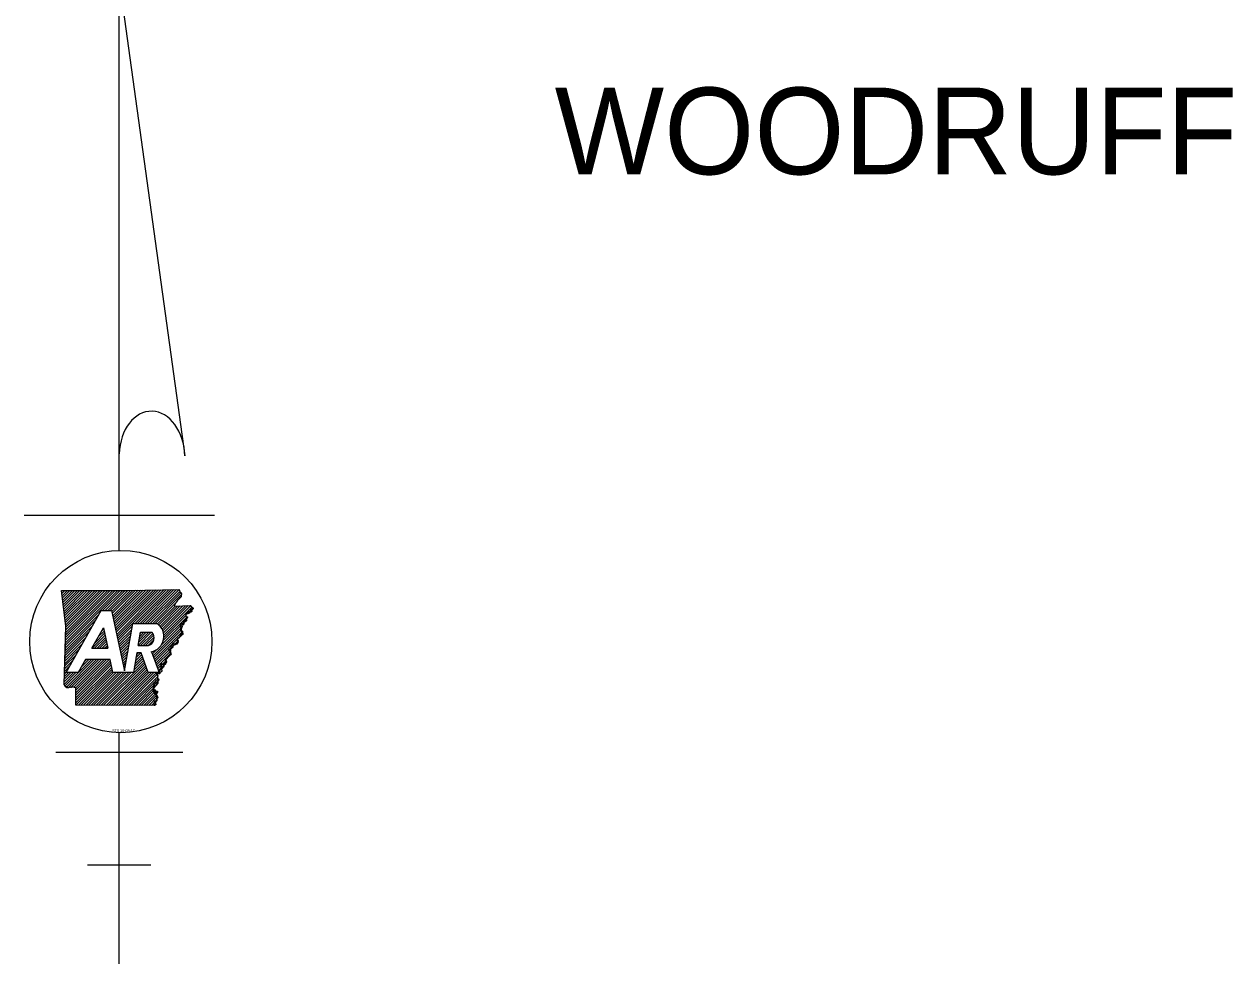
# Model space of a CAD drawing. Extents: x -24122 to 24238, y -8840 to 11381.
# Drawn here: x -13734 to -10389, y 3625 to 6225 of the extents above; entities that cross this region are included whole.
import ezdxf

# ---------------------------------------------------------------- set-up
doc = ezdxf.new("R2010")
doc.units = 0
doc.layers.add('R_Annotation', color=7, linetype='Continuous')
doc.layers.add('R_Border', color=7, linetype='Continuous')

msp = doc.modelspace()

# ---------------------------------------------------------------- linework, layer by layer
at = {"layer": 'R_Annotation'}
for p, q in [((-13470.5, 6345), (-13288.7, 5030.9)), ((-13470.5, 4769.2), (-13470.5, 6345)), ((-13733.7, 4866.6), (-13207.4, 4866.6)), ((-13630.2, 4656.3), (-13628, 4658.4)), ((-13629.4, 4650.1), (-13621, 4658.4)), ((-13628.6, 4643.9), (-13614.1, 4658.4)), ((-13627.9, 4637.7), (-13607.1, 4658.4)), ((-13627.1, 4631.5), (-13600.2, 4658.4)), ((-13626.3, 4625.3), (-13593.2, 4658.4)), ((-13625.6, 4619.1), (-13586.2, 4658.4)), ((-13624.8, 4612.9), (-13579.3, 4658.4)), ((-13624, 4606.7), (-13572.3, 4658.4)), ((-13623.2, 4600.5), (-13565.4, 4658.4)), ((-13622.5, 4594.3), (-13558.4, 4658.4)), ((-13621.7, 4588.1), (-13551.4, 4658.4)), ((-13620.9, 4581.9), (-13544.5, 4658.4)), ((-13620.2, 4575.7), (-13537.5, 4658.4)), ((-13619.9, 4506.3), (-13467.7, 4658.5)), ((-13619.7, 4513.5), (-13474.7, 4658.5)), ((-13619.4, 4520.7), (-13481.7, 4658.5)), ((-13619.4, 4569.5), (-13530.5, 4658.4)), ((-13619.2, 4527.9), (-13488.7, 4658.5)), ((-13619, 4535.1), (-13495.6, 4658.5)), ((-13618.7, 4542.3), (-13502.6, 4658.4)), ((-13618.6, 4563.4), (-13523.6, 4658.4)), ((-13618.5, 4549.5), (-13509.6, 4658.4)), ((-13618.2, 4556.8), (-13516.6, 4658.4)), ((-13516.5, 4602.8), (-13460.7, 4658.5)), ((-13509.5, 4602.8), (-13453.8, 4658.6)), ((-13502.5, 4602.8), (-13446.7, 4658.6)), ((-13495.6, 4602.8), (-13439.7, 4658.7)), ((-13491.2, 4600.2), (-13432.6, 4658.8)), ((-13490, 4594.4), (-13425.5, 4658.9)), ((-13488.8, 4588.7), (-13418.4, 4659)), ((-13487.6, 4583), (-13411.3, 4659.2)), ((-13486.3, 4577.2), (-13404.3, 4659.3)), ((-13485.1, 4571.5), (-13397.2, 4659.4)), ((-13483.9, 4565.7), (-13390.1, 4659.5)), ((-13482.6, 4560), (-13383, 4659.6)), ((-13481.4, 4554.3), (-13376, 4659.7)), ((-13480.2, 4548.5), (-13368.9, 4659.8)), ((-13479, 4542.8), (-13361.8, 4659.9)), ((-13477.7, 4537), (-13354.7, 4660)), ((-13476.5, 4531.3), (-13347.6, 4660.2)), ((-13475.3, 4525.6), (-13340.5, 4660.3)), ((-13426.9, 4567), (-13333.4, 4660.5)), ((-13419.9, 4567), (-13326.3, 4660.7)), ((-13413, 4567), (-13319.1, 4660.8)), ((-13406, 4567), (-13312, 4661)), ((-13399, 4567), (-13304.9, 4661.2)), ((-13392.1, 4567), (-13303.3, 4655.8)), ((-13385.1, 4567), (-13299.9, 4652.2)), ((-13378.1, 4567), (-13299, 4646.1)), ((-13371.2, 4567), (-13314.9, 4623.2)), ((-13354.6, 4555.7), (-13294.3, 4616)), ((-13352, 4551.3), (-13286.9, 4616.4)), ((-13349.9, 4546.5), (-13279.6, 4616.8)), ((-13348.3, 4541.1), (-13273, 4616.4)), ((-13620.2, 4499.1), (-13526.2, 4593.1)), ((-13617.8, 4431.2), (-13520.7, 4602.8)), ((-13520.7, 4602.8), (-13491.8, 4602.8)), ((-13364.8, 4566.4), (-13316.3, 4614.9)), ((-13361, 4563.2), (-13309, 4615.3)), ((-13357.6, 4559.6), (-13301.6, 4615.6)), ((-13348.8, 4519.7), (-13285.6, 4582.9)), ((-13347.4, 4535.1), (-13269.7, 4612.7)), ((-13347.3, 4528.1), (-13286.4, 4589.1)), ((-13272.8, 4602.6), (-13266.5, 4609)), ((-13620.6, 4484.7), (-13544.4, 4561)), ((-13620.4, 4491.9), (-13535.3, 4577)), ((-13546.4, 4498.5), (-13514.6, 4554.7)), ((-13519.5, 4545.9), (-13513.9, 4551.6)), ((-13474.1, 4519.8), (-13434.5, 4559.4)), ((-13472.8, 4514.1), (-13436, 4550.9)), ((-13433.2, 4567), (-13365.7, 4567)), ((-13377.5, 4477), (-13300.3, 4554.3)), ((-13354.8, 4506.7), (-13301.6, 4559.9)), ((-13293.4, 4568.2), (-13284.8, 4576.8)), ((-13621.1, 4470.3), (-13562.5, 4528.9)), ((-13620.9, 4477.5), (-13553.4, 4544.9)), ((-13546, 4498.5), (-13510.2, 4534.3)), ((-13539.1, 4498.5), (-13509, 4528.6)), ((-13537.7, 4513.8), (-13511.5, 4540.1)), ((-13532.1, 4498.5), (-13507.8, 4522.9)), ((-13528.6, 4529.9), (-13512.7, 4545.8)), ((-13525.1, 4498.5), (-13506.6, 4517.1)), ((-13471.6, 4508.4), (-13437.5, 4542.5)), ((-13470.4, 4502.6), (-13438.9, 4534.1)), ((-13469.1, 4496.9), (-13440.4, 4525.6)), ((-13467.9, 4491.1), (-13441.9, 4517.2)), ((-13418.5, 4506.1), (-13381.9, 4542.8)), ((-13417.1, 4514.5), (-13388.8, 4542.8)), ((-13415.6, 4523), (-13395.8, 4542.8)), ((-13414.1, 4531.4), (-13402.8, 4542.8)), ((-13412.7, 4539.8), (-13409.7, 4542.8)), ((-13412.2, 4542.8), (-13380.5, 4542.8)), ((-13411.5, 4506.1), (-13378, 4539.7)), ((-13404.6, 4506.1), (-13375.6, 4535.1)), ((-13397.6, 4506.1), (-13374.3, 4529.4)), ((-13390.6, 4506.1), (-13374.9, 4521.8)), ((-13375.7, 4471.9), (-13299, 4548.6)), ((-13373.8, 4466.9), (-13297.7, 4542.9)), ((-13371.9, 4461.8), (-13296.4, 4537.3)), ((-13320.2, 4506.5), (-13310.4, 4516.3)), ((-13621.6, 4455.9), (-13580.7, 4496.8)), ((-13621.4, 4463.1), (-13571.6, 4512.8)), ((-13546.4, 4498.5), (-13502.6, 4498.5)), ((-13518.2, 4498.5), (-13505.3, 4511.4)), ((-13511.2, 4498.5), (-13504.1, 4505.7)), ((-13504.2, 4498.5), (-13502.9, 4499.9)), ((-13466.7, 4485.4), (-13443.3, 4508.7)), ((-13465.5, 4479.7), (-13444.8, 4500.3)), ((-13464.2, 4473.9), (-13446.3, 4491.9)), ((-13463, 4468.2), (-13447.8, 4483.4)), ((-13424.5, 4471.8), (-13410.6, 4485.8)), ((-13423.1, 4480.3), (-13417.6, 4485.8)), ((-13410.4, 4485.8), (-13422.1, 4485.8)), ((-13418.5, 4506.1), (-13389.6, 4506.1)), ((-13390.2, 4431.2), (-13410.4, 4485.8)), ((-13381.8, 4488.7), (-13360.6, 4431.2)), ((-13381.3, 4487.2), (-13379.2, 4489.3)), ((-13379.4, 4482.1), (-13366.2, 4495.4)), ((-13370, 4456.7), (-13328.2, 4498.5)), ((-13368.1, 4451.6), (-13329, 4490.7)), ((-13366.3, 4446.5), (-13329.8, 4483)), ((-13622.3, 4434.3), (-13608, 4448.6)), ((-13622.1, 4441.5), (-13598.9, 4464.6)), ((-13621.8, 4448.7), (-13589.8, 4480.7)), ((-13620.8, 4394), (-13547.6, 4467.2)), ((-13616.7, 4391.2), (-13540.6, 4467.2)), ((-13611.7, 4389.2), (-13533.7, 4467.2)), ((-13603.4, 4390.5), (-13526.7, 4467.2)), ((-13596.3, 4390.6), (-13519.7, 4467.2)), ((-13590.9, 4389.1), (-13512.8, 4467.2)), ((-13590.6, 4375.4), (-13498.8, 4467.2)), ((-13590.6, 4382.4), (-13505.8, 4467.2)), ((-13590.6, 4368.5), (-13495.2, 4463.9)), ((-13590.6, 4361.5), (-13493.9, 4458.2)), ((-13590.5, 4354.6), (-13492.7, 4452.4)), ((-13564.1, 4467.2), (-13584.5, 4431.2)), ((-13576.6, 4445.1), (-13554.6, 4467.2)), ((-13567.5, 4461.2), (-13561.5, 4467.2)), ((-13495.9, 4467.2), (-13564.1, 4467.2)), ((-13520.9, 4340.7), (-13401.1, 4460.5)), ((-13513.9, 4340.7), (-13399.2, 4455.4)), ((-13507, 4340.6), (-13397.3, 4450.3)), ((-13461.8, 4462.5), (-13449.2, 4475)), ((-13460.5, 4456.7), (-13450.7, 4466.6)), ((-13459.3, 4451), (-13452.2, 4458.1)), ((-13458.1, 4445.2), (-13453.6, 4449.7)), ((-13430.4, 4438.1), (-13402.9, 4465.6)), ((-13428.9, 4446.5), (-13404.8, 4470.7)), ((-13427.5, 4455), (-13406.7, 4475.7)), ((-13426, 4463.4), (-13408.6, 4480.8)), ((-13364.4, 4441.4), (-13343, 4462.8)), ((-13362.5, 4436.3), (-13346, 4452.8)), ((-13623.4, 4398.4), (-13590.6, 4431.2)), ((-13623.3, 4405.5), (-13597.5, 4431.2)), ((-13623, 4412.7), (-13604.5, 4431.2)), ((-13622.8, 4419.9), (-13611.5, 4431.2)), ((-13622.5, 4427.1), (-13617.1, 4432.5)), ((-13584.5, 4431.2), (-13617.8, 4431.2)), ((-13590.5, 4347.6), (-13491.5, 4446.7)), ((-13590.4, 4340.8), (-13490.2, 4440.9)), ((-13583.5, 4340.8), (-13489, 4435.2)), ((-13576.5, 4340.8), (-13486.1, 4431.2)), ((-13569.5, 4340.8), (-13479.1, 4431.2)), ((-13562.6, 4340.7), (-13472.1, 4431.2)), ((-13555.6, 4340.7), (-13465.2, 4431.2)), ((-13548.7, 4340.7), (-13458.2, 4431.2)), ((-13541.7, 4340.7), (-13451.2, 4431.2)), ((-13534.8, 4340.7), (-13444.3, 4431.2)), ((-13527.8, 4340.7), (-13437.3, 4431.2)), ((-13500, 4340.6), (-13395.4, 4445.2)), ((-13493.1, 4340.6), (-13393.5, 4440.1)), ((-13431.6, 4431.2), (-13488.2, 4431.2)), ((-13486.1, 4340.6), (-13391.7, 4435)), ((-13479.1, 4340.6), (-13388.6, 4431.2)), ((-13472.2, 4340.6), (-13381.6, 4431.2)), ((-13465.2, 4340.6), (-13374.6, 4431.2)), ((-13458.3, 4340.6), (-13367.7, 4431.2)), ((-13456.9, 4439.5), (-13455.1, 4441.3)), ((-13451.3, 4340.6), (-13365.3, 4426.6)), ((-13444.4, 4340.5), (-13365, 4419.9)), ((-13360.6, 4431.2), (-13390.2, 4431.2)), ((-13437.4, 4340.5), (-13364.7, 4413.2)), ((-13430.5, 4340.5), (-13364.4, 4406.6)), ((-13423.5, 4340.5), (-13375.8, 4388.2)), ((-13416.6, 4340.5), (-13373.7, 4383.4)), ((-13409.6, 4340.5), (-13371.5, 4378.6)), ((-13402.6, 4340.5), (-13369.4, 4373.7)), ((-13395.7, 4340.5), (-13367.2, 4368.9)), ((-13388.7, 4340.5), (-13365.4, 4363.8)), ((-13381.8, 4340.4), (-13368.6, 4353.6)), ((-13374.8, 4340.4), (-13371.7, 4343.5)), ((-13470.5, 3625.5), (-13470.5, 4265.1)), ((-13646, 4210.7), (-13295.1, 4210.7)), ((-13558.3, 3899.1), (-13382.8, 3899.1))]:
    msp.add_line(p, q, dxfattribs=at)
for points in [[(-13630.5, 4658.4), (-13534.4, 4658.4), (-13450, 4658.6), (-13350.5, 4660.1), (-13304.4, 4661.2)], [(-13630.5, 4658.4), (-13534.4, 4658.4), (-13450, 4658.6), (-13350.5, 4660.1), (-13304.4, 4661.2)], [(-13619.8, 4509), (-13618.2, 4559.7), (-13630.5, 4658.4)], [(-13623.5, 4398.4), (-13618.1, 4559.7), (-13630.5, 4658.4)], [(-13274.2, 4617), (-13265.9, 4608.3), (-13286.6, 4591.3), (-13284.4, 4574.1), (-13302.2, 4562.4), (-13296.1, 4535.9), (-13309.8, 4523.4), (-13311, 4509.8), (-13327.7, 4503.8), (-13330.3, 4478.2), (-13342.3, 4465.3), (-13348.1, 4446), (-13365.5, 4430.1), (-13364.2, 4401.9), (-13376, 4388.6), (-13365.2, 4364.4), (-13372.7, 4340.4)], [(-13318.7, 4614.8), (-13273.6, 4617.1)], [(-13318.7, 4614.8), (-13273.6, 4617.1)], [(-13491.8, 4602.8), (-13456.1, 4435.8), (-13433.2, 4567)], [(-13514.6, 4554.7), (-13502.6, 4498.5)], [(-13418.5, 4506.1), (-13412.2, 4542.8)], [(-13623.5, 4398.4), (-13619.8, 4509)], [(-13422.1, 4485.8), (-13431.6, 4431.2)], [(-13488.2, 4431.2), (-13495.9, 4467.2)], [(-13372.7, 4340.4), (-13590.5, 4340.8), (-13590.6, 4388.9)], [(-13372.7, 4340.4), (-13590.5, 4340.8), (-13590.6, 4388.9)]]:
    msp.add_lwpolyline(points, dxfattribs=at)
for centre, major_axis, ratio, start_param, end_param in [((-13379.7, 5028.1), (-3.9, 126.3), 0.719778, 4.712385, 7.768526), ((-13390.8, 4531.3), (-43.6, 0), 0.999987, 1.777838, 4.099264), ((-13396.5, 4527.3), (-22.3, 0), 0.999987, 1.887169, 3.90762)]:
    msp.add_ellipse(centre, major_axis=major_axis, ratio=ratio, start_param=start_param, end_param=end_param, dxfattribs=at)
msp.add_ellipse((-13466.4, 4517.1), major_axis=(252.1, 0), ratio=0.999976, dxfattribs=at)
for points in [[(-13304.4, 4661.2), (-13304.1, 4658.6), (-13303.3, 4657.2), (-13303.2, 4654.7), (-13302.2, 4653.6), (-13300.4, 4652.5), (-13298.9, 4650.8), (-13298.5, 4648.8), (-13299, 4646.8), (-13299.1, 4644.4), (-13299.4, 4642.4), (-13299.8, 4640.6), (-13301.1, 4639.1), (-13302.5, 4638), (-13303.7, 4636.8), (-13304.6, 4635.4), (-13306.2, 4634), (-13307.7, 4632.5), (-13309, 4631.2), (-13310.3, 4629.6), (-13310.9, 4627.7), (-13312.2, 4626.4), (-13313.3, 4625.2), (-13314.7, 4623.6), (-13315.4, 4622), (-13316.7, 4620.2), (-13317.1, 4618.4), (-13317.9, 4617), (-13318, 4616.7)], [(-13304.4, 4661.2), (-13304.1, 4658.6), (-13303.3, 4657.2), (-13303.2, 4654.7), (-13302.2, 4653.6), (-13300.4, 4652.6), (-13298.9, 4650.8), (-13298.5, 4648.8), (-13299, 4646.7), (-13299.1, 4644.4), (-13299.4, 4642.4), (-13299.7, 4640.6), (-13301.1, 4639.1), (-13302.5, 4638), (-13303.8, 4636.7), (-13304.7, 4635.4), (-13306.2, 4634), (-13307.7, 4632.5), (-13309, 4631.2), (-13310.2, 4629.6), (-13310.8, 4627.7), (-13312.2, 4626.4), (-13313.3, 4625.2), (-13314.7, 4623.6), (-13315.4, 4622), (-13316.8, 4620.2), (-13317.1, 4618.4), (-13318, 4617), (-13318, 4616.7)], [(-13274.2, 4617), (-13273.6, 4617.1), (-13271.6, 4615), (-13270.7, 4613.1), (-13269.3, 4612.2), (-13267.8, 4611.6), (-13266.7, 4610.3), (-13266, 4608.7), (-13266.4, 4607.4), (-13268.1, 4607.3), (-13269.9, 4607), (-13271.7, 4607.1), (-13273.1, 4605.9), (-13271.8, 4604.3), (-13270.1, 4602.8), (-13269.6, 4601.2), (-13270.5, 4599.7), (-13272.5, 4598.8), (-13274.3, 4598.1), (-13276, 4596.7), (-13276.8, 4595.3), (-13278.6, 4594.7), (-13280.5, 4594.2), (-13282.1, 4594), (-13284, 4593.6), (-13285.9, 4592.7), (-13286.6, 4591.2), (-13286.4, 4589), (-13286.5, 4586.7), (-13284.5, 4585.9), (-13282.8, 4585.9), (-13281.1, 4585), (-13281.3, 4583.7), (-13282.5, 4582), (-13284, 4580.7), (-13285.5, 4580.1), (-13286.9, 4578.8), (-13286.4, 4577.5), (-13285.2, 4576.7), (-13284.3, 4575.4), (-13284.4, 4574.1), (-13285.8, 4573.2), (-13287.4, 4573.6), (-13288.5, 4575.1), (-13289.8, 4575.5), (-13290.9, 4576.1), (-13292.2, 4575.3), (-13292.2, 4573.6), (-13292.7, 4571.8), (-13292.3, 4570.4), (-13291.8, 4568.5), (-13291.8, 4567.1), (-13292.3, 4565), (-13293.3, 4562.9), (-13294.5, 4562.3), (-13295, 4564.5), (-13295.2, 4566.4), (-13295.9, 4567.5), (-13296.9, 4567.5), (-13298.1, 4566.6), (-13299.5, 4565.2), (-13301.2, 4563.8), (-13302.2, 4562.3), (-13301.7, 4560.5), (-13300.4, 4560), (-13299.4, 4560.3), (-13298.8, 4561.5), (-13297.9, 4561.7), (-13296.9, 4559.8)], [(-13296.9, 4559.8), (-13296.6, 4558.1), (-13297.6, 4556.3), (-13298, 4554.5), (-13297.9, 4552.6), (-13299.8, 4551.6), (-13301.4, 4550.4), (-13300.4, 4549), (-13298.6, 4547.7), (-13296.9, 4546.7), (-13295.8, 4545.6), (-13295.5, 4543.2), (-13295.2, 4541.7), (-13294.5, 4539.5), (-13294.3, 4538), (-13295.4, 4536.3), (-13296.6, 4535.9), (-13298, 4536.3), (-13299.5, 4536.4), (-13300.7, 4535.3), (-13301.6, 4533.6), (-13302.5, 4531.9), (-13303.2, 4530.5), (-13303.9, 4528.9), (-13305.1, 4527.1), (-13306.7, 4526.9), (-13308.6, 4526.4), (-13309.8, 4525.1), (-13309.6, 4522.9), (-13308.5, 4521.4), (-13307.7, 4519.6), (-13307.1, 4518), (-13307.4, 4515.9), (-13308.2, 4514.4), (-13309.3, 4513.5), (-13309.8, 4511.7), (-13310.6, 4510.2), (-13311.2, 4509.7), (-13312.7, 4509.9), (-13314.2, 4510.1), (-13315.5, 4510), (-13316.7, 4509.4), (-13318, 4509.8), (-13319.3, 4511.2), (-13320.4, 4512.3), (-13321.6, 4512.7), (-13322.9, 4512.1), (-13323, 4510.1), (-13322.5, 4508.1), (-13321.9, 4505.4), (-13322.5, 4503.7), (-13322.7, 4500.9)], [(-13322.7, 4500.9), (-13324.7, 4499.4), (-13325.7, 4497.7), (-13331, 4498.2), (-13330.8, 4496.3), (-13332.7, 4495.4), (-13334.4, 4494.2), (-13333.4, 4492.7), (-13331.6, 4491.4), (-13329.8, 4490.4), (-13328.7, 4489.4), (-13328.4, 4486.9), (-13328.1, 4485.4), (-13327.5, 4483.2), (-13327.3, 4481.8), (-13328.4, 4480), (-13329.6, 4479.7), (-13330.9, 4480.1), (-13332.4, 4480.2), (-13333.7, 4479), (-13334.6, 4477.3), (-13335.5, 4475.6), (-13336.1, 4474.2), (-13336.8, 4472.7), (-13338.1, 4470.9), (-13339.7, 4470.6), (-13341.6, 4470.1), (-13342.7, 4468.9), (-13342.5, 4466.6), (-13341.5, 4465.2), (-13340.7, 4463.3), (-13340.1, 4461.7), (-13340.3, 4459.7), (-13341.2, 4458.2), (-13342.2, 4457.3), (-13342.7, 4455.4), (-13343.5, 4454), (-13344.2, 4453.5), (-13345.6, 4453.7), (-13347.2, 4453.9), (-13348.5, 4453.8), (-13349.7, 4453.2), (-13351, 4453.6), (-13352.3, 4455), (-13353.4, 4456.1), (-13354.6, 4456.5), (-13355.8, 4455.8), (-13356, 4453.8), (-13355.4, 4451.9), (-13354.9, 4449.1), (-13355.4, 4447.5), (-13355.6, 4444.7)], [(-13363.6, 4422.3), (-13364.2, 4420.9), (-13364.9, 4418.6), (-13364.7, 4416.6), (-13363.8, 4414.9), (-13362.4, 4413.9), (-13360.8, 4412.5), (-13360.9, 4410.4), (-13361.8, 4409.7), (-13363.9, 4410.2), (-13365.5, 4410.9), (-13366.9, 4410.5), (-13368.7, 4409.6), (-13370.1, 4409.4), (-13370, 4406.6), (-13368.2, 4404.5), (-13366.6, 4404.5), (-13364.7, 4404.3), (-13364.1, 4402.2), (-13365.2, 4400.4), (-13366.9, 4399.5), (-13369.2, 4400.6), (-13370.8, 4401.7), (-13372.4, 4402.8), (-13374.4, 4403.3), (-13375.6, 4403.1), (-13376.1, 4400.6), (-13375.1, 4398.3), (-13373.6, 4396.8), (-13372.2, 4394.8), (-13372.4, 4393.2), (-13373.5, 4392.9), (-13375.4, 4392.4), (-13376.5, 4391.9), (-13376.8, 4391.4), (-13376.2, 4389.3), (-13375.7, 4387.2), (-13375.7, 4385.5), (-13376.3, 4384), (-13377.3, 4381.6), (-13377.2, 4380.1), (-13376.5, 4379.3), (-13375.6, 4379.5), (-13374.4, 4380.4), (-13373.6, 4381.3), (-13373, 4382.5), (-13371.8, 4383.5), (-13370.2, 4382.6), (-13369.9, 4380.8), (-13370.7, 4379.2), (-13372, 4378.4), (-13373.5, 4377.9), (-13374.7, 4376.6), (-13374.4, 4375), (-13373.5, 4374.2), (-13371.3, 4374.6), (-13369.8, 4375.3), (-13368.9, 4376), (-13367.9, 4377.1), (-13367.4, 4378.1), (-13366.6, 4379.2), (-13365.2, 4379.5), (-13364.6, 4378.6), (-13364.9, 4376.6), (-13365.7, 4374.6), (-13366.8, 4373.1), (-13368.1, 4372), (-13369.6, 4369.5), (-13369.3, 4367.3), (-13368.7, 4365.4), (-13367.9, 4364), (-13366.5, 4364.2), (-13364.9, 4364.4), (-13363.9, 4363.7), (-13364, 4362), (-13365.2, 4360.4), (-13366.3, 4358.8), (-13366.9, 4356.7), (-13366.7, 4355.2), (-13366.7, 4353.9), (-13367.2, 4352.4), (-13368, 4351.5), (-13370.2, 4351.6), (-13372.5, 4351.8), (-13373.8, 4351.1), (-13373.5, 4349.1), (-13372.2, 4347.6), (-13371.2, 4346.9), (-13369.9, 4345.2), (-13369.3, 4343.8), (-13369.4, 4342.6), (-13370.3, 4341.6), (-13372.7, 4340.4)], [(-13363.6, 4422.3), (-13364.2, 4420.9), (-13364.9, 4418.6), (-13364.7, 4416.6), (-13363.8, 4414.9), (-13362.4, 4413.9), (-13360.8, 4412.5), (-13360.9, 4410.4), (-13361.8, 4409.7), (-13363.9, 4410.2), (-13365.5, 4410.9), (-13366.9, 4410.5), (-13368.7, 4409.6), (-13370.1, 4409.4), (-13370, 4406.6), (-13368.2, 4404.5), (-13366.6, 4404.5), (-13364.7, 4404.3), (-13364.1, 4402.2), (-13365.2, 4400.4), (-13366.9, 4399.5), (-13369.2, 4400.6), (-13370.8, 4401.7), (-13372.4, 4402.8), (-13374.4, 4403.3), (-13375.6, 4403.1), (-13376.1, 4400.6), (-13375.1, 4398.3), (-13373.6, 4396.8), (-13372.2, 4394.8), (-13372.4, 4393.2), (-13373.5, 4392.9), (-13375.4, 4392.4), (-13376.5, 4391.9), (-13376.8, 4391.4), (-13376.2, 4389.3), (-13375.7, 4387.2), (-13375.7, 4385.5), (-13376.3, 4384), (-13377.3, 4381.6), (-13377.2, 4380.1), (-13376.5, 4379.3), (-13375.6, 4379.5), (-13374.4, 4380.4), (-13373.6, 4381.3), (-13373, 4382.5), (-13371.8, 4383.5), (-13370.2, 4382.6), (-13369.9, 4380.8), (-13370.7, 4379.2), (-13372, 4378.4), (-13373.5, 4377.9), (-13374.7, 4376.6), (-13374.4, 4375), (-13373.5, 4374.2), (-13371.3, 4374.6), (-13369.8, 4375.3), (-13368.9, 4376), (-13367.9, 4377.1), (-13367.4, 4378.1), (-13366.6, 4379.2), (-13365.2, 4379.5), (-13364.6, 4378.6), (-13364.9, 4376.6), (-13365.7, 4374.6), (-13366.8, 4373.1), (-13368.1, 4372), (-13369.6, 4369.5), (-13369.3, 4367.3), (-13368.7, 4365.4), (-13367.9, 4364), (-13366.5, 4364.2), (-13364.9, 4364.4), (-13363.9, 4363.7), (-13364, 4362), (-13365.2, 4360.4), (-13366.3, 4358.8), (-13366.9, 4356.7), (-13366.7, 4355.2), (-13366.7, 4353.9), (-13367.2, 4352.4), (-13368, 4351.5), (-13370.2, 4351.6), (-13372.5, 4351.8), (-13373.8, 4351.1), (-13373.5, 4349.1), (-13372.2, 4347.6), (-13371.2, 4346.9), (-13369.9, 4345.2), (-13369.3, 4343.8), (-13369.4, 4342.6), (-13370.3, 4341.6), (-13372.7, 4340.4)], [(-13355.6, 4444.7), (-13355.8, 4444.6), (-13356.8, 4443.3), (-13356.2, 4441.2), (-13353.9, 4440.3), (-13352.9, 4438.3), (-13352.8, 4436.6), (-13353.6, 4434.1), (-13354.6, 4433), (-13356.7, 4432.5), (-13358.3, 4432.2), (-13358.5, 4429.5), (-13359.3, 4428.1), (-13360.5, 4427.7), (-13362.3, 4428.6), (-13363.4, 4429), (-13364.7, 4429.6), (-13366.3, 4430.6), (-13367.6, 4430.4), (-13367.2, 4427.8), (-13367.1, 4427.7), (-13365.7, 4425.7), (-13364.3, 4424.2), (-13363.6, 4422.3)], [(-13355.6, 4444.7), (-13355.8, 4444.6), (-13356.8, 4443.3), (-13356.2, 4441.2), (-13353.9, 4440.3), (-13352.9, 4438.3), (-13352.8, 4436.6), (-13353.6, 4434.1), (-13354.6, 4433), (-13356.7, 4432.5), (-13358.3, 4432.2), (-13358.5, 4429.5), (-13359.3, 4428.1), (-13360.5, 4427.7), (-13362.3, 4428.6), (-13363.4, 4429), (-13364.7, 4429.6), (-13366.3, 4430.6), (-13367.6, 4430.4), (-13367.2, 4427.8), (-13367.1, 4427.7), (-13365.7, 4425.7), (-13364.3, 4424.2), (-13363.6, 4422.3)], [(-13590.6, 4388.9), (-13590.4, 4388.8), (-13591.5, 4389.5), (-13593.1, 4390.3), (-13594.8, 4390.4), (-13597, 4390.7), (-13598.8, 4390.9), (-13600.7, 4392.1), (-13602.7, 4390.9), (-13605, 4389.9), (-13606.3, 4391), (-13608, 4390.2), (-13609.2, 4390.6), (-13611.3, 4389.2), (-13613.3, 4389.7), (-13614.7, 4389.3), (-13616.5, 4389.3), (-13616.8, 4391.4), (-13618.6, 4391.6), (-13620.1, 4392.5), (-13621.1, 4394.6), (-13621.8, 4396.2), (-13623.5, 4398.4)], [(-13590.6, 4388.9), (-13590.4, 4388.7), (-13591.5, 4389.5), (-13593.1, 4390.3), (-13594.8, 4390.4), (-13597, 4390.7), (-13598.8, 4390.9), (-13600.7, 4392.1), (-13602.8, 4390.8), (-13605, 4389.9), (-13606.3, 4390.9), (-13608, 4390.2), (-13609.2, 4390.6), (-13611.3, 4389.2), (-13613.3, 4389.7), (-13614.7, 4389.3), (-13616.5, 4389.3), (-13616.8, 4391.4), (-13618.6, 4391.7), (-13620.1, 4392.5), (-13621.1, 4394.6), (-13621.8, 4396.2), (-13623.5, 4398.4)]]:
    msp.add_spline(points, degree=3, dxfattribs=at)

# ---------------------------------------------------------------- texts
msp.add_text('STS 10-03-17', height=7.288, dxfattribs=at).set_placement((-13490.5, 4267.1))
at = {"layer": 'R_Border'}
msp.add_text('WOODRUFF', height=240, dxfattribs=at).set_placement((-12265.7, 5809.8))

doc.saveas('drawing.dxf')
